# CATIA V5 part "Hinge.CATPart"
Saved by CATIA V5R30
Part number: 1586A22_SURFACE-MOUNT HINGE WITH HOLES
Bounding box of the stored display mesh (mm): x -19.332 to 19.332, y -16.002 to 16.002, z -3.048 to 2.944
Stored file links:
  D:\OneDrive\OneDrive - Carleton University\Courses\aero2001\Design Project\3D Models\Hinge.CATPart
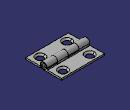
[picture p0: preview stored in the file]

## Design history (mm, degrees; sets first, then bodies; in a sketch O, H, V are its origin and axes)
Set1
  DatumSurface1 to DatumSurface70
Body1 (main body)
